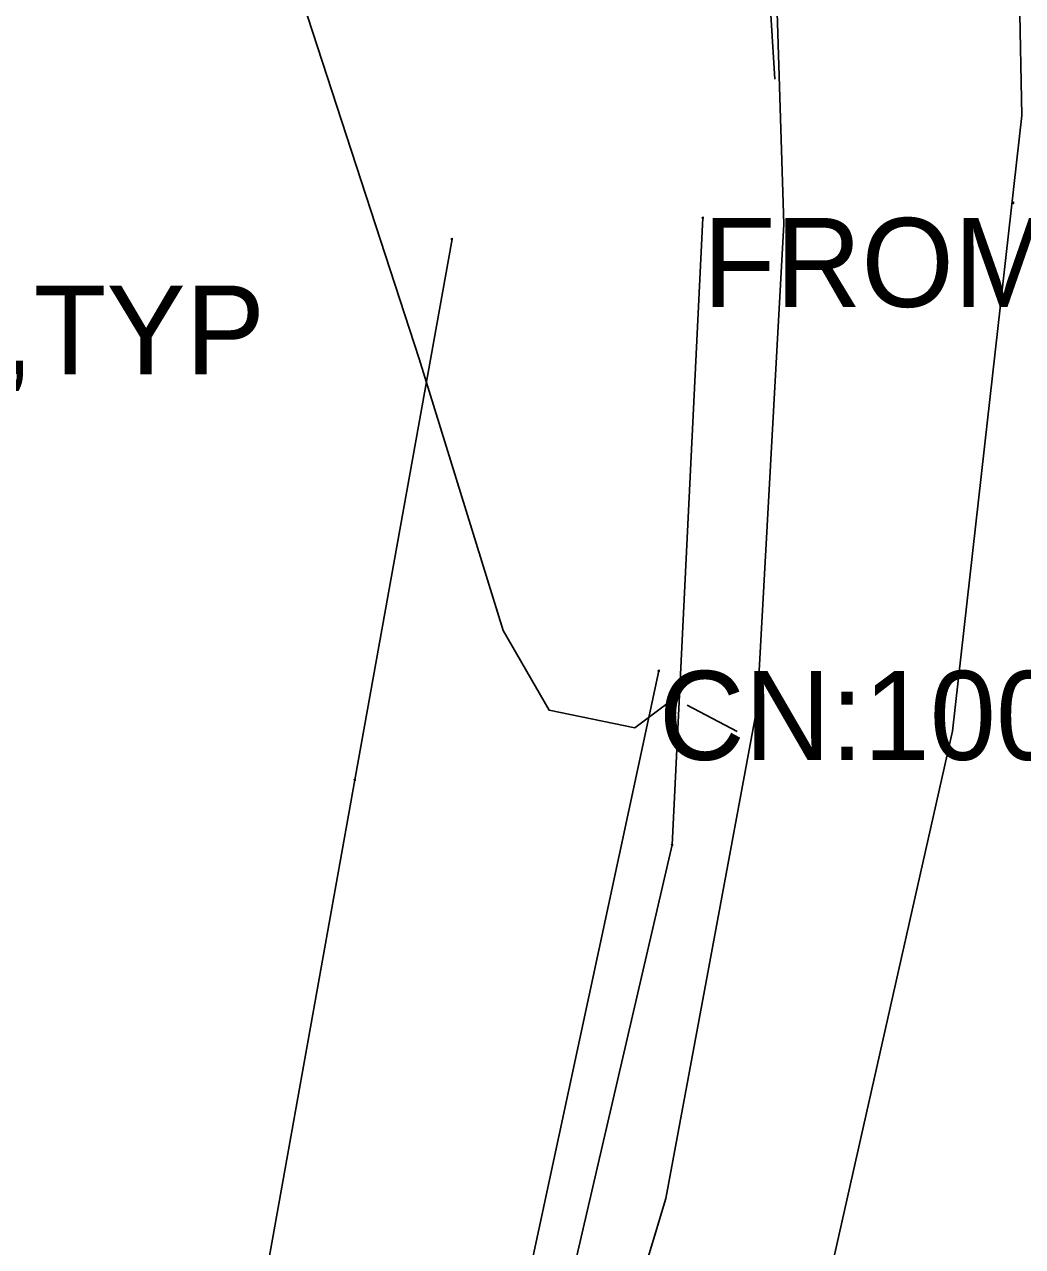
# Model space of a CAD drawing. Extents: x 997398 to 1003416, y 334596 to 337085.
# Drawn here: x 999547.1 to 999603.2, y 336416.9 to 336485.6 of the extents above; entities that cross this region are included whole.
import ezdxf

# ---------------------------------------------------------------- set-up
doc = ezdxf.new("R2010")
doc.units = 0
for name, color, linetype in [('S_CURB', 7, 'Continuous'), ('S_DRG_PT_SYM', 7, 'Continuous'), ('S_EDGE_CONCRETE', 7, 'Continuous'), ('S_EDGE_PAVEMENT', 7, 'Continuous'), ('S_FIBER_OPTIC_CABLE', 7, 'Continuous'), ('S_GAS_UTILITIES', 7, 'Continuous'), ('S_GAS_UTILITIES_ANNOT', 7, 'Continuous'), ('S_GRD_PT_SYM', 7, 'Continuous'), ('S_PAVEMENT_CROWN', 7, 'Continuous'), ('S_SHOULDER', 7, 'Continuous'), ('S_SIDE_DRAIN', 7, 'Continuous'), ('S_SIDE_DRAIN_ANNOT', 7, 'Continuous'), ('S_UTL_PT_SYM', 7, 'Continuous'), ('S_VENT_ANNOT', 7, 'Continuous')]:
    doc.layers.add(name, color=color, linetype=linetype)

msp = doc.modelspace()

# ---------------------------------------------------------------- linework, layer by layer
at = {"layer": 'S_CURB'}
msp.add_lwpolyline([(999499.195, 336612.107), (999510.843, 336606.264), (999522.491, 336600.42), (999529.871, 336580.074), (999537.252, 336559.729), (999541.599, 336547.787), (999545.946, 336535.846), (999550.293, 336523.904), (999554.639, 336511.963), (999561.972, 336489.389), (999569.304, 336466.815), (999574.031, 336451.55), (999576.612, 336447.065), (999581.429, 336446.088), (999583.605, 336447.704)], dxfattribs=at)
at = {"layer": 'S_DRG_PT_SYM'}
msp.add_lwpolyline([(999582.785, 336449.278), (999582.785, 336449.328), (999582.785, 336449.278), (999582.735, 336449.278), (999582.785, 336449.278), (999582.785, 336449.228), (999582.785, 336449.278), (999582.835, 336449.278)], dxfattribs=at)
at = {"layer": 'S_EDGE_CONCRETE'}
msp.add_lwpolyline([(999584.374, 336447.361), (999587.194, 336445.875)], dxfattribs=at)
at = {"layer": 'S_EDGE_PAVEMENT'}
for points in [[(999589.819, 336474.393), (999589.177, 336494.633), (999588.535, 336514.873), (999584.747, 336534.225), (999580.958, 336553.576), (999571.859, 336575.319), (999562.76, 336597.061), (999553.058, 336612.719), (999534.161, 336628.268), (999517.282, 336637.068), (999500.403, 336645.868)], [(999588.319, 336447.251), (999589.069, 336460.822), (999589.819, 336474.393)], [(999554.17, 336334.665), (999558.594, 336346.502), (999563.018, 336358.339), (999567.442, 336370.176), (999571.867, 336382.013), (999577.521, 336400.817), (999583.175, 336419.622), (999585.747, 336433.436), (999588.319, 336447.251)]]:
    msp.add_lwpolyline(points, dxfattribs=at)
at = {"layer": 'S_FIBER_OPTIC_CABLE'}
for p, q in [((999571.157, 336473.555), (999565.702, 336443.165)), ((999565.702, 336443.165), (999560.22, 336412.681))]:
    msp.add_line(p, q, dxfattribs=at)
at = {"layer": 'S_GAS_UTILITIES'}
for p, q in [((999585.261, 336474.74), (999583.541, 336439.505)), ((999583.541, 336439.505), (999575.599, 336405.372))]:
    msp.add_line(p, q, dxfattribs=at)
at = {"layer": 'S_GRD_PT_SYM'}
msp.add_lwpolyline([(999602.72, 336475.595), (999602.72, 336475.645), (999602.72, 336475.595), (999602.67, 336475.595), (999602.72, 336475.595), (999602.72, 336475.545), (999602.72, 336475.595), (999602.77, 336475.595)], dxfattribs=at)
at = {"layer": 'S_PAVEMENT_CROWN'}
for points in [[(999603.199, 336480.509), (999602.933, 336493.782), (999602.666, 336507.054), (999602.399, 336520.327), (999602.132, 336533.6), (999599.821, 336557.938), (999601.509, 336573.766), (999603.196, 336589.594)], [(999599.292, 336445.895), (999601.246, 336463.202), (999603.199, 336480.509)], [(999563.08, 336330.783), (999567.638, 336342.849), (999572.195, 336354.915), (999576.753, 336366.981), (999581.31, 336379.047), (999586.968, 336397.667), (999592.627, 336416.287), (999595.959, 336431.091), (999599.292, 336445.895)]]:
    msp.add_lwpolyline(points, dxfattribs=at)
at = {"layer": 'S_SHOULDER'}
msp.add_lwpolyline([(999499.085, 336645.203), (999516.842, 336635.736), (999534.599, 336626.269), (999551.478, 336608.213), (999559.078, 336596.6), (999566.677, 336584.986), (999573.807, 336565.854), (999580.936, 336546.722), (999584.243, 336528.845), (999587.549, 336510.968), (999588.428, 336496.758), (999589.307, 336482.548)], dxfattribs=at)
at = {"layer": 'S_SIDE_DRAIN'}
msp.add_line((999570.119, 336390.407), (999582.785, 336449.278), dxfattribs=at)
at = {"layer": 'S_UTL_PT_SYM'}
for points in [[(999602.72, 336475.595), (999602.72, 336475.645), (999602.72, 336475.595), (999602.67, 336475.595), (999602.72, 336475.595), (999602.72, 336475.545), (999602.72, 336475.595), (999602.77, 336475.595)], [(999585.261, 336474.74), (999585.261, 336474.79), (999585.261, 336474.74), (999585.211, 336474.74), (999585.261, 336474.74), (999585.261, 336474.69), (999585.261, 336474.74), (999585.311, 336474.74)], [(999571.157, 336473.555), (999571.157, 336473.605), (999571.157, 336473.555), (999571.107, 336473.555), (999571.157, 336473.555), (999571.157, 336473.505), (999571.157, 336473.555), (999571.208, 336473.555)], [(999565.702, 336443.165), (999565.702, 336443.215), (999565.702, 336443.165), (999565.652, 336443.165), (999565.702, 336443.165), (999565.702, 336443.115), (999565.702, 336443.165), (999565.752, 336443.165)], [(999583.541, 336439.505), (999583.541, 336439.555), (999583.541, 336439.505), (999583.491, 336439.505), (999583.541, 336439.505), (999583.541, 336439.455), (999583.541, 336439.505), (999583.591, 336439.505)]]:
    msp.add_lwpolyline(points, dxfattribs=at)

# ---------------------------------------------------------------- texts
at = {"layer": 'S_GAS_UTILITIES_ANNOT'}
msp.add_text('FROM NW', height=5, dxfattribs=at).set_placement((999585.261, 336469.74))
at = {"layer": 'S_SIDE_DRAIN_ANNOT'}
msp.add_text('CN:100% FILL,CRUSHED', height=5, dxfattribs=at).set_placement((999582.785, 336444.278))
at = {"layer": 'S_VENT_ANNOT'}
msp.add_text("CTR OF 2X2' LID,TYP", height=5, dxfattribs=at).set_placement((999493.607, 336465.943))

doc.saveas('drawing.dxf')
